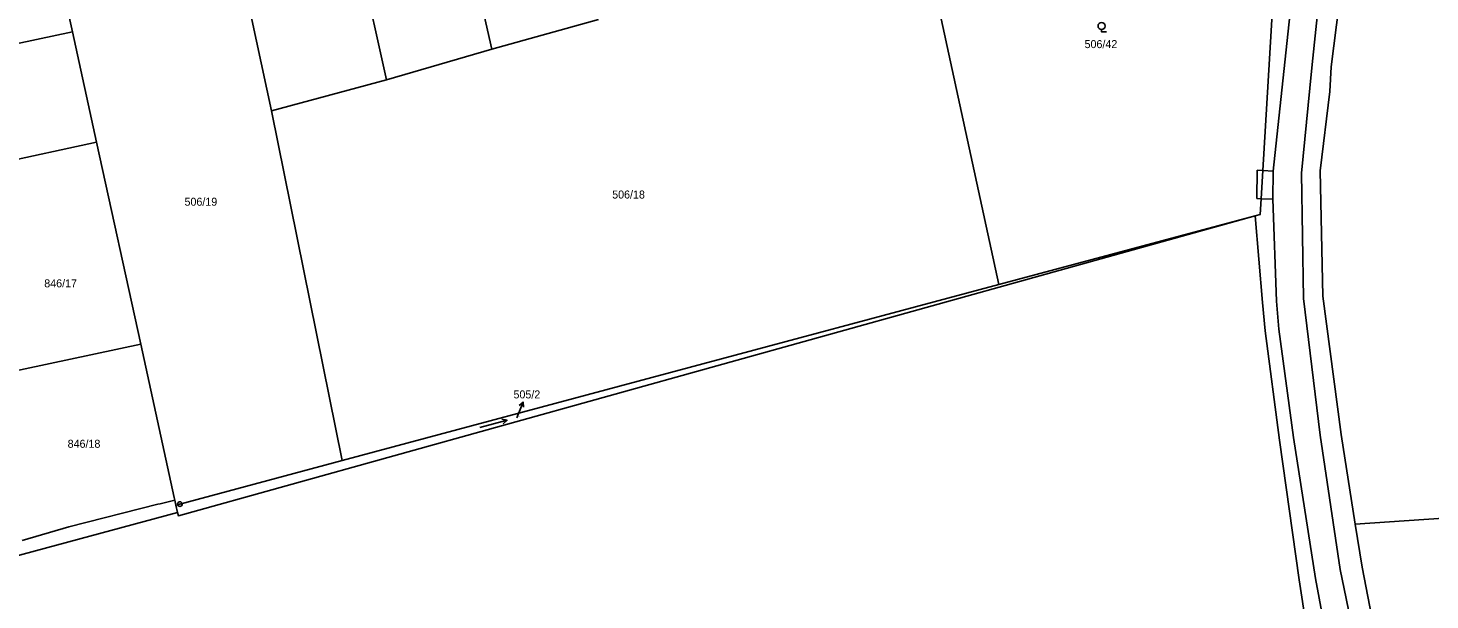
# Model space of a CAD drawing. Extents: x -725765 to -723182, y -1052705 to -1049154.
# Drawn here: x -724986 to -724688.1, y -1051438.8 to -1051317.3 of the extents above; entities that cross this region are included whole.
import ezdxf

# ---------------------------------------------------------------- set-up
doc = ezdxf.new("R2010")
doc.units = 0
for name, color, linetype in [('Vrstva 1', 7, 'Continuous'), ('Vrstva 16', 7, 'Continuous'), ('Vrstva 18', 7, 'Continuous'), ('Vrstva 25', 7, 'Continuous'), ('Vrstva 4', 7, 'Continuous'), ('Vrstva 52', 7, 'Continuous')]:
    doc.layers.add(name, color=color, linetype=linetype)

msp = doc.modelspace()

# ---------------------------------------------------------------- linework, layer by layer
at = {"layer": 'Vrstva 1'}
for points in [[(-724898.83, -1051271.67), (-724887.44, -1051321.75)], [(-724920.71, -1051279.19), (-724909.84, -1051328.29)], [(-724942.84, -1051294.98), (-724934.23, -1051334.87)], [(-724723.66, -1051347.54), (-724720.73, -1051298.85)], [(-724979.85, -1051302.94), (-724976.54, -1051318.1)], [(-724709.12, -1051325.51), (-724706.33, -1051303.7)], [(-725019.16, -1051327.2), (-724976.54, -1051318.1)], [(-724976.54, -1051318.1), (-724971.42, -1051341.57)], [(-724887.44, -1051321.75), (-724864.8, -1051315.46)], [(-724791.96, -1051315.34), (-724779.72, -1051371.82)], [(-724909.84, -1051328.29), (-724887.44, -1051321.75)], [(-724709.36, -1051330.78), (-724709.12, -1051325.51)], [(-724934.23, -1051334.87), (-724909.84, -1051328.29)], [(-724711.42, -1051347.65), (-724709.36, -1051330.78)], [(-724934.23, -1051334.87), (-724919.28, -1051409.21)], [(-724992.44, -1051346.06), (-724971.42, -1051341.57)], [(-724971.42, -1051341.57), (-724962.06, -1051384.47)], [(-724724.02, -1051353.56), (-724723.66, -1051347.54)], [(-724710.86, -1051374.28), (-724711.42, -1051347.65)], [(-724724.23, -1051356.94), (-724724.02, -1051353.56)], [(-724725.23, -1051357.22), (-724724.23, -1051356.94)], [(-724954.06, -1051420.94), (-724725.23, -1051357.22)], [(-724779.72, -1051371.82), (-724725.23, -1051357.22)], [(-724725.23, -1051357.22), (-724723.73, -1051375.64)], [(-724919.28, -1051409.21), (-724779.72, -1051371.82)], [(-724707, -1051403.67), (-724710.86, -1051374.28)], [(-724723.13, -1051381.63), (-724723.73, -1051375.64)], [(-724723.13, -1051381.63), (-724720.08, -1051404.85)], [(-724991.9, -1051390.85), (-724962.06, -1051384.47)], [(-724962.06, -1051384.47), (-724954.95, -1051417.03)], [(-724703.99, -1051422.72), (-724707, -1051403.67)], [(-724720.08, -1051404.85), (-724715.93, -1051434.53)], [(-724953.72, -1051418.44), (-724919.28, -1051409.21)], [(-724611.23, -1051416.43), (-724703.99, -1051422.72)], [(-724977.34, -1051423.27), (-724958.45, -1051418.48)], [(-724958.45, -1051418.48), (-724957.92, -1051418.37)], [(-724954.83, -1051417.6), (-724957.92, -1051418.37)], [(-724954.95, -1051417.03), (-724954.83, -1051417.6)], [(-724954.83, -1051417.6), (-724954.59, -1051418.67)], [(-724954.59, -1051418.67), (-724953.72, -1051418.44)], [(-724954.59, -1051418.67), (-724954.23, -1051420.23)], [(-724954.23, -1051420.23), (-725019.91, -1051437.94)], [(-724954.23, -1051420.23), (-724954.06, -1051420.94)], [(-724987.27, -1051426.15), (-724977.34, -1051423.27)], [(-724702.54, -1051431.88), (-724703.99, -1051422.72)], [(-724694, -1051475.83), (-724702.54, -1051431.88)], [(-724715.93, -1051434.53), (-724711.18, -1051465.47)]]:
    msp.add_lwpolyline(points, dxfattribs=at)
at = {"layer": 'Vrstva 16'}
msp.add_lwpolyline([(-724882.12, -1051400.11), (-724881.9, -1051399.55)], dxfattribs=at)
at = {"layer": 'Vrstva 25'}
for points in [[(-724757.9, -1051317.62), (-724757.9, -1051318.12), (-724756.88, -1051318.12)], [(-724881.9, -1051399.55), (-724880.8, -1051396.76)], [(-724881.63, -1051397.51), (-724880.8, -1051396.76), (-724880.7, -1051397.87)], [(-724890.01, -1051402.2), (-724884.21, -1051400.64)], [(-724885.31, -1051400.42), (-724884.21, -1051400.64), (-724885.05, -1051401.38)]]:
    msp.add_lwpolyline(points, dxfattribs=at)
for centre, radius in [((-724757.9, -1051316.87), 0.75), ((-724953.72, -1051418.44), 0.5), ((-724953.72, -1051418.44), 0.032)]:
    msp.add_circle(centre, radius, dxfattribs=at)
at = {"layer": 'Vrstva 4'}
for points in [[(-724721.4, -1051347.68), (-724716.64, -1051302.65)], [(-724710.8, -1051302.69), (-724713.16, -1051325.04)], [(-724713.16, -1051325.04), (-724713.67, -1051330.1)], [(-724713.67, -1051330.1), (-724715.39, -1051348.12)], [(-724724.9, -1051353.53), (-724724.85, -1051347.46)], [(-724724.85, -1051347.46), (-724723.66, -1051347.54)], [(-724723.66, -1051347.54), (-724721.4, -1051347.68)], [(-724721.48, -1051353.63), (-724721.4, -1051347.68)], [(-724715.39, -1051348.12), (-724714.98, -1051374.74)], [(-724724.9, -1051353.53), (-724724.02, -1051353.56)], [(-724724.02, -1051353.56), (-724721.48, -1051353.63)], [(-724720.74, -1051375.36), (-724721.48, -1051353.63)], [(-724711.44, -1051403.77), (-724714.98, -1051374.74)], [(-724720.74, -1051375.36), (-724720.23, -1051381.27)], [(-724720.23, -1051381.27), (-724717.1, -1051404.28)], [(-724717.1, -1051404.28), (-724712.46, -1051434.26)], [(-724707.19, -1051432.33), (-724711.44, -1051403.77)], [(-724712.46, -1051434.26), (-724705.43, -1051471.87)], [(-724697.96, -1051476.87), (-724707.19, -1051432.33)]]:
    msp.add_lwpolyline(points, dxfattribs=at)
at = {"layer": 'Vrstva 52'}
for points in [[(-724661.75, -1051050.29), (-724651.62, -1051161.43), (-724663.49, -1051147.21), (-724676.38, -1051113.58), (-724671.46, -1051135.3), (-724668.53, -1051157.94), (-724657.88, -1051179.95), (-724652.47, -1051191.12), (-724669.81, -1051186.83), (-724677.68, -1051194.15), (-724680.8, -1051202.26), (-724683.66, -1051209.67), (-724689.19, -1051228.95), (-724692.56, -1051246.84), (-724705.66, -1051300.92), (-724706.33, -1051303.7), (-724709.12, -1051325.51), (-724709.36, -1051330.78), (-724711.42, -1051347.65), (-724710.86, -1051374.28), (-724707, -1051403.67), (-724703.99, -1051422.72), (-724702.54, -1051431.88), (-724694, -1051475.83)], [(-724720.73, -1051298.85), (-724723.66, -1051347.54), (-724724.02, -1051353.56), (-724724.23, -1051356.94), (-724725.23, -1051357.22)], [(-725355.1, -1051531.23), (-725333, -1051525.34), (-725272.53, -1051508.42), (-725203.03, -1051489.25), (-725134.1, -1051470.08), (-725074.47, -1051452.88), (-725019.91, -1051437.94), (-724954.23, -1051420.23), (-724954.06, -1051420.94), (-724725.23, -1051357.22)], [(-724725.23, -1051357.22), (-724779.72, -1051371.82), (-724919.28, -1051409.21), (-724953.72, -1051418.44), (-724954.59, -1051418.67), (-724954.83, -1051417.6), (-724957.92, -1051418.37), (-724958.45, -1051418.48), (-724977.34, -1051423.27), (-724987.27, -1051426.15)], [(-724725.23, -1051357.22), (-724723.73, -1051375.64), (-724723.13, -1051381.63), (-724720.08, -1051404.85), (-724715.93, -1051434.53), (-724711.18, -1051465.47), (-724710.64, -1051468.99), (-724710.34, -1051469.83), (-724709.16, -1051473.19), (-724707.54, -1051476.71), (-724699.73, -1051499.75), (-724685.53, -1051539.31), (-724683.28, -1051545.23), (-724664.86, -1051596.4), (-724648.71, -1051642.6)]]:
    msp.add_lwpolyline(points, dxfattribs=at)

# ---------------------------------------------------------------- texts
at = {"layer": 'Vrstva 16'}
msp.add_text('505/2', height=1.7, dxfattribs=at).set_placement((-724882.85, -1051395.99))
at = {"layer": 'Vrstva 18'}
for s, height, p in [('506/42', 1.7, (-724761.51, -1051321.56)), ('506/19', 1.7, (-724952.75, -1051355.05)), ('506/18', 1.7, (-724861.88, -1051353.52)), ('846/17', 1.7, (-724982.55, -1051372.39)), ('505/2', 0.1, (-724881.92, -1051399.91)), ('846/18', 1.7, (-724977.58, -1051406.48))]:
    msp.add_text(s, height=height, dxfattribs=at).set_placement(p)

doc.saveas('drawing.dxf')
